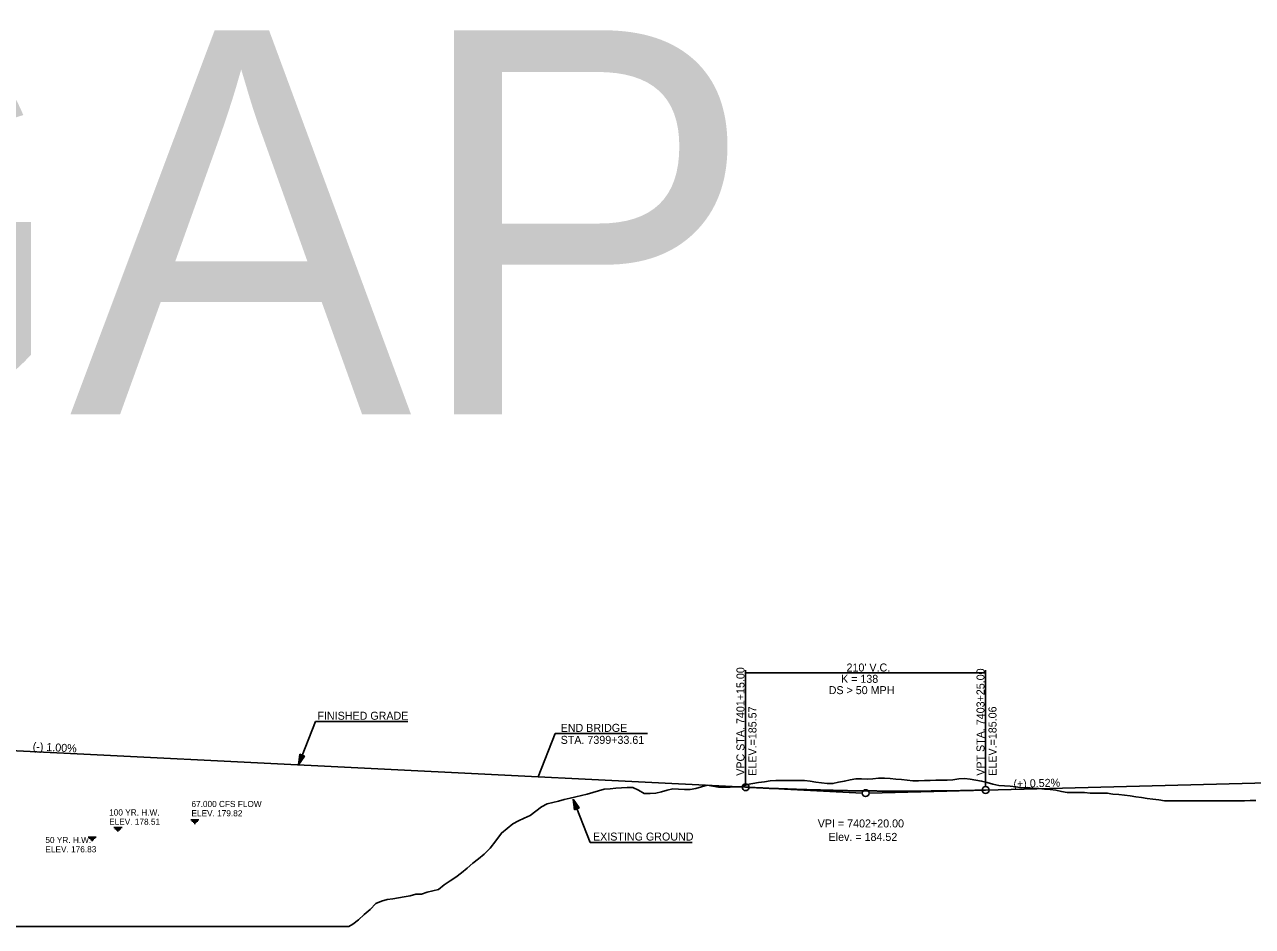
# Model space of a CAD drawing. Extents: x 69 to 2003113, y 512 to 837401.
# Drawn here: x 1917847 to 1918922, y 833588 to 834377 of the extents above; entities that cross this region are included whole.
import ezdxf

# ---------------------------------------------------------------- set-up
doc = ezdxf.new("R2010")
doc.units = 0
for name, color, linetype in [('BR_BORDER LINES', 7, 'Continuous'), ('BR_CENTER LINE BASELINE', 7, 'Continuous'), ('BR_CONCRETE', 7, 'Continuous'), ('BR_GRID DOTS', 7, 'Continuous'), ('BR_GRID LINES', 7, 'Continuous'), ('BR_TEXT', 7, 'Continuous'), ('RD_PD_ALT1_TrvlWay', 7, 'Continuous'), ('RD_SHT_IplotShp', 7, 'Continuous')]:
    doc.layers.add(name, color=color, linetype=linetype)

msp = doc.modelspace()

# ---------------------------------------------------------------- linework, layer by layer
at = {"layer": 'BR_CENTER LINE BASELINE'}
for p, q in [((1918512.2, 833708.3), (1918580.1, 833704.9)), ((1918654.1, 833706.6), (1918586.1, 833704.8))]:
    msp.add_line(p, q, dxfattribs=at)
msp.add_circle((1918583.1, 833704.8), 3, dxfattribs=at)
at = {"layer": 'BR_GRID DOTS'}
for p, q in [((1918478.1, 833812.5), (1918478.1, 833713)), ((1918478.1, 833810), (1918688.1, 833810)), ((1918688.1, 833812.5), (1918688.1, 833710.5))]:
    msp.add_line(p, q, dxfattribs=at)
for centre in [(1918478.1, 833710), (1918688.1, 833707.5)]:
    msp.add_circle(centre, 3, dxfattribs=at)
at = {"layer": 'BR_GRID LINES'}
for p, q in [((1917803.1, 833743.8), (1918478.1, 833710)), ((1918688.1, 833707.5), (1918992.4, 833715.3))]:
    msp.add_line(p, q, dxfattribs=at)
msp.add_spline([(1918478.1, 833710), (1918482.3, 833709.8), (1918486.5, 833709.6), (1918490.7, 833709.4), (1918494.9, 833709.2), (1918499.1, 833709), (1918503.3, 833708.9), (1918507.5, 833708.7), (1918511.7, 833708.5), (1918515.9, 833708.4), (1918520.1, 833708.2), (1918524.3, 833708.1), (1918528.5, 833708), (1918532.7, 833707.8), (1918536.9, 833707.7), (1918541.1, 833707.6), (1918545.3, 833707.5), (1918549.5, 833707.4), (1918553.7, 833707.3), (1918557.9, 833707.2), (1918562.1, 833707.1), (1918566.3, 833707), (1918570.5, 833706.9), (1918574.7, 833706.9), (1918578.9, 833706.8), (1918583.1, 833706.8), (1918587.3, 833706.7), (1918591.5, 833706.7), (1918595.7, 833706.6), (1918599.9, 833706.6), (1918604.1, 833706.6), (1918608.3, 833706.6), (1918612.5, 833706.6), (1918616.7, 833706.6), (1918620.9, 833706.6), (1918625.1, 833706.6), (1918629.3, 833706.6), (1918633.5, 833706.6), (1918637.7, 833706.6), (1918641.9, 833706.7), (1918646.1, 833706.7), (1918650.3, 833706.8), (1918654.5, 833706.8), (1918658.7, 833706.9), (1918662.9, 833706.9), (1918667.1, 833707), (1918671.3, 833707.1), (1918675.5, 833707.2), (1918679.7, 833707.3), (1918683.9, 833707.4), (1918688.1, 833707.5)], degree=3, dxfattribs=at)
at = {"layer": 'BR_TEXT'}
for points in [[(1918194.5, 833616.5), (1918199.5, 833618.1), (1918204.5, 833619.3), (1918209.5, 833620.4), (1918214.5, 833624.7), (1918219.5, 833628), (1918224.5, 833631.3), (1918229.5, 833635.2), (1918234.5, 833639.3), (1918239.5, 833643.4), (1918244.5, 833647.4), (1918249.5, 833651.5), (1918254.5, 833656.7), (1918259.5, 833663.2), (1918264.5, 833669.8), (1918269.5, 833673.9), (1918274.5, 833677.9), (1918279.5, 833680.5), (1918284.5, 833683), (1918289.5, 833685.1), (1918294.5, 833688.9), (1918299.5, 833692.8), (1918304.5, 833695.5), (1918309.5, 833696.7), (1918314.5, 833697.8), (1918319.5, 833699.1), (1918324.5, 833700.3), (1918329.5, 833701.5), (1918334.5, 833702.6), (1918339.5, 833703.9), (1918344.5, 833705.3), (1918349.5, 833706.8), (1918354.5, 833708.2), (1918359.5, 833708.6), (1918364.5, 833709.1), (1918369.5, 833709.5), (1918374.5, 833709.6), (1918379.5, 833709.7), (1918384.5, 833707.4), (1918389.5, 833704.4), (1918394.5, 833704.4), (1918399.5, 833704.8), (1918404.5, 833706), (1918409.5, 833707.3), (1918414.5, 833708.5), (1918419.5, 833708.4), (1918424.5, 833708.1), (1918429.5, 833707.9), (1918434.5, 833708.9), (1918439.5, 833710.4), (1918444.5, 833711.8), (1918449.5, 833711), (1918454.5, 833709.9), (1918459.5, 833710), (1918464.5, 833710.1), (1918469.5, 833710.2), (1918474.5, 833710.3), (1918479.5, 833712.3), (1918484.5, 833713.2), (1918489.5, 833714), (1918494.5, 833714.8), (1918499.5, 833715.6), (1918504.5, 833715.9), (1918509.5, 833715.9), (1918514.5, 833715.9), (1918519.5, 833715.9), (1918524.5, 833715.8), (1918529.5, 833715.8), (1918534.5, 833715.2), (1918539.5, 833714.5), (1918544.5, 833713.8), (1918549.5, 833713.1), (1918554.5, 833713.2), (1918559.5, 833714.3), (1918564.5, 833715.4), (1918569.5, 833716.4), (1918574.5, 833717.3), (1918579.5, 833717.2), (1918584.5, 833717.1), (1918589.5, 833717.3), (1918594.5, 833717.8), (1918599.5, 833718), (1918604.5, 833717.5), (1918609.5, 833717), (1918614.5, 833716.6), (1918619.5, 833716.1), (1918624.5, 833715.5), (1918629.5, 833715.6), (1918634.5, 833715.8), (1918639.5, 833715.9), (1918644.5, 833716), (1918649.5, 833716), (1918654.5, 833716), (1918659.5, 833716.5), (1918664.5, 833717.2), (1918669.5, 833717.5), (1918674.5, 833716.9), (1918679.5, 833716.2), (1918684.5, 833715.4), (1918689.5, 833714), (1918694.5, 833712.6)], [(1918694.5, 833712.6), (1918699.5, 833711.5), (1918704.5, 833711.2), (1918709.5, 833710.9), (1918714.5, 833710.4), (1918719.5, 833709.5), (1918724.5, 833709.6), (1918729.5, 833709.2), (1918734.5, 833708.8), (1918739.5, 833708.4), (1918744.5, 833707.9), (1918749.5, 833707.3), (1918754.5, 833706.3), (1918759.5, 833705.5), (1918764.5, 833705.4), (1918769.5, 833705.4), (1918774.5, 833705.3), (1918779.5, 833704.8), (1918784.5, 833704.9), (1918789.5, 833704.9), (1918794.5, 833704.9), (1918799.5, 833704), (1918804.5, 833703.6), (1918809.5, 833703), (1918814.5, 833702.3), (1918819.5, 833701.6), (1918824.5, 833700.9), (1918829.5, 833700.1), (1918834.5, 833699.5), (1918839.5, 833698.8), (1918844.5, 833698.2), (1918849.5, 833698.2), (1918854.5, 833698.1), (1918859.5, 833698.1), (1918864.5, 833698), (1918869.5, 833698), (1918874.5, 833698.1), (1918879.5, 833698), (1918884.5, 833698), (1918889.5, 833698), (1918894.5, 833698), (1918899.5, 833698.1), (1918904.5, 833698.1), (1918909.5, 833698.1), (1918914.5, 833698.1), (1918919.5, 833698.3), (1918924.5, 833698.4)], [(1917791.3, 833588.2), (1918130.9, 833588.2), (1918134.5, 833590.1), (1918139.5, 833594.1), (1918144.5, 833598.5), (1918149.5, 833602.9), (1918154.5, 833608.2), (1918159.5, 833610.4), (1918164.5, 833611.6), (1918169.5, 833612.4), (1918174.5, 833613.3), (1918179.5, 833614.1), (1918184.5, 833614.9), (1918189.5, 833616.4), (1918194.5, 833616.5)]]:
    msp.add_lwpolyline(points, dxfattribs=at)
at = {"layer": 'RD_PD_ALT1_TrvlWay'}
for p, q in [((1918086.9, 833729.6), (1918101.8, 833767.6)), ((1918101.8, 833767.6), (1918182.6, 833767.6)), ((1918296.7, 833719.1), (1918311.6, 833757)), ((1918311.6, 833757), (1918392.4, 833757)), ((1918086.9, 833729.6), (1918088.1, 833738.8)), ((1918090.2, 833738), (1918086.9, 833729.6)), ((1918086.9, 833729.6), (1918092.3, 833737.2)), ((1918088.1, 833738.8), (1918092.3, 833737.2)), ((1918327.2, 833699.5), (1918342.1, 833661.6)), ((1918330.5, 833691.2), (1918327.2, 833699.5)), ((1918327.2, 833699.5), (1918332.6, 833692)), ((1918327.2, 833699.5), (1918328.4, 833690.3)), ((1918328.4, 833690.3), (1918332.6, 833692)), ((1917992.7, 833681.3), (1917999.8, 833681.3)), ((1917993.7, 833680.3), (1917998.8, 833680.3)), ((1917994.7, 833679.3), (1917997.8, 833679.3)), ((1917925.4, 833674.7), (1917932.6, 833674.7)), ((1917926.4, 833673.7), (1917931.6, 833673.7)), ((1917927.4, 833672.7), (1917930.6, 833672.7)), ((1917928.4, 833671.7), (1917929.6, 833671.7)), ((1917995.7, 833678.3), (1917996.8, 833678.3)), ((1917902.9, 833666.3), (1917910, 833666.3)), ((1917903.9, 833665.3), (1917909, 833665.3)), ((1917904.9, 833664.3), (1917908, 833664.3)), ((1917905.9, 833663.3), (1917907, 833663.3)), ((1918342.1, 833661.6), (1918431.3, 833661.6))]:
    msp.add_line(p, q, dxfattribs=at)
for points in [[(1918090.1, 833737.9), (1918087, 833730.1), (1918090, 833738), (1918087.1, 833730.5), (1918089.9, 833738), (1918087.1, 833730.8), (1918089.8, 833738), (1918087.1, 833731.1), (1918089.8, 833738), (1918087.2, 833731.6), (1918089.6, 833738.1), (1918087.3, 833732.1), (1918089.5, 833738.1), (1918087.4, 833732.5), (1918089.4, 833738.2), (1918087.4, 833733), (1918089.3, 833738.2), (1918087.5, 833733.4), (1918089.3, 833738.3), (1918087.5, 833733.7), (1918089.1, 833738.3), (1918087.6, 833734.2), (1918089, 833738.3), (1918087.7, 833734.8), (1918088.9, 833738.4), (1918087.7, 833735.2), (1918088.8, 833738.4), (1918087.8, 833735.9), (1918088.7, 833738.4), (1918087.9, 833736.4), (1918088.6, 833738.5), (1918087.9, 833736.8), (1918088.5, 833738.5), (1918088, 833737.2), (1918088.4, 833738.6), (1918088, 833737.7), (1918088.3, 833738.6), (1918088.1, 833738.2), (1918088.2, 833738.6)], [(1918087.2, 833730.1), (1918090.2, 833737.9), (1918087.3, 833730.4), (1918090.3, 833737.8), (1918087.5, 833730.6), (1918090.4, 833737.8), (1918087.7, 833730.8), (1918090.4, 833737.8), (1918087.9, 833731.1), (1918090.5, 833737.8), (1918088, 833731.3), (1918090.6, 833737.7), (1918088.2, 833731.6), (1918090.7, 833737.7), (1918088.5, 833732), (1918090.8, 833737.6), (1918088.7, 833732.3), (1918090.9, 833737.7), (1918088.9, 833732.7), (1918091, 833737.6), (1918089.2, 833733), (1918091.1, 833737.6), (1918089.4, 833733.3), (1918091.1, 833737.5), (1918089.7, 833733.8), (1918091.2, 833737.5), (1918090, 833734), (1918091.3, 833737.5), (1918090.3, 833734.4), (1918091.4, 833737.4), (1918090.5, 833734.8), (1918091.5, 833737.4), (1918090.7, 833735.1), (1918091.6, 833737.3), (1918091, 833735.4), (1918091.6, 833737.3), (1918091.2, 833735.9), (1918091.8, 833737.3), (1918091.4, 833736.2), (1918091.9, 833737.2), (1918091.6, 833736.3), (1918092, 833737.1), (1918092.1, 833737.1), (1918092, 833737.1)], [(1918330.4, 833691.2), (1918327.3, 833699), (1918330.3, 833691.2), (1918327.4, 833698.6), (1918330.2, 833691.2), (1918327.4, 833698.4), (1918330.1, 833691.1), (1918327.4, 833698), (1918330, 833691.1), (1918327.5, 833697.5), (1918329.9, 833691), (1918327.6, 833697), (1918329.8, 833691), (1918327.6, 833696.6), (1918329.7, 833691), (1918327.7, 833696.2), (1918329.6, 833691), (1918327.8, 833695.8), (1918329.6, 833690.9), (1918327.8, 833695.4), (1918329.4, 833690.9), (1918327.8, 833694.9), (1918329.3, 833690.8), (1918328, 833694.3), (1918329.2, 833690.7), (1918328, 833693.9), (1918329.1, 833690.7), (1918328.1, 833693.3), (1918329, 833690.7), (1918328.2, 833692.8), (1918328.9, 833690.6), (1918328.2, 833692.3), (1918328.8, 833690.6), (1918328.2, 833691.9), (1918328.7, 833690.5), (1918328.3, 833691.4), (1918328.6, 833690.5), (1918328.4, 833690.9), (1918328.5, 833690.5)], [(1918327.4, 833699), (1918330.5, 833691.3), (1918327.6, 833698.7), (1918330.6, 833691.3), (1918327.8, 833698.5), (1918330.7, 833691.3), (1918327.9, 833698.3), (1918330.7, 833691.4), (1918328.1, 833698), (1918330.8, 833691.4), (1918328.3, 833697.8), (1918330.9, 833691.4), (1918328.5, 833697.5), (1918331, 833691.4), (1918328.8, 833697.1), (1918331.1, 833691.5), (1918329, 833696.8), (1918331.2, 833691.5), (1918329.2, 833696.5), (1918331.3, 833691.5), (1918329.5, 833696.2), (1918331.4, 833691.6), (1918329.7, 833695.8), (1918331.4, 833691.6), (1918330, 833695.4), (1918331.5, 833691.6), (1918330.2, 833695.1), (1918331.6, 833691.6), (1918330.5, 833694.7), (1918331.7, 833691.7), (1918330.8, 833694.3), (1918331.8, 833691.8), (1918331, 833694), (1918331.8, 833691.9), (1918331.3, 833693.7), (1918331.9, 833691.9), (1918331.5, 833693.2), (1918332.1, 833691.9), (1918331.7, 833693), (1918332.2, 833691.9), (1918331.9, 833692.8), (1918332.3, 833692.1), (1918332.4, 833692), (1918332.3, 833692)]]:
    msp.add_lwpolyline(points, dxfattribs=at)

# ---------------------------------------------------------------- texts
at = {"layer": 'BR_BORDER LINES'}
msp.add_text('NOGAP', height=336, dxfattribs=at).set_placement((1916863.1, 834036.2))
at = {"layer": 'BR_CENTER LINE BASELINE'}
for s, rotation, p in [('(-) 1.00%', 357.1375, (1917854.3, 833742.3)), ('(+) 0.52%', 1.479, (1918712.5, 833709.5))]:
    msp.add_text(s, height=7, rotation=rotation, dxfattribs=at).set_placement(p)
at = {"layer": 'BR_CONCRETE'}
for s, p in [('VPC STA. 7401+15.00 ', (1918477.1, 833720)), ('VPT STA. 7403+25.00 ', (1918687.1, 833720)), ('ELEV.=185.57', (1918487.6, 833720)), ('ELEV.=185.06', (1918697.6, 833720))]:
    msp.add_text(s, height=7, rotation=90, dxfattribs=at).set_placement(p)
at = {"layer": 'BR_GRID DOTS'}
for s, p in [('K = 138', (1918561.6, 833801.3)), ("210' V.C.", (1918566.4, 833811.2)), ('DS > 50 MPH', (1918550.8, 833791.4))]:
    msp.add_text(s, height=7, dxfattribs=at).set_placement(p)
at = {"layer": 'RD_PD_ALT1_TrvlWay'}
for s, height, p in [('FINISHED GRADE', 7, (1918103.5, 833769)), ('EXISTING GROUND', 7, (1918344.6, 833663.3)), ('50 YR. H.W.', 5.4, (1917865.5, 833661.1)), ('ELEV. 176.83', 5.4, (1917865.5, 833653))]:
    msp.add_text(s, height=height, dxfattribs=at).set_placement(p)
for s, p in [('100 YR. H.W.', (1917921.3, 833685.2)), ('67.000 CFS FLOW', (1917993.3, 833692.6)), ('ELEV. 179.82', (1917993.3, 833684.5)), ('ELEV. 178.51', (1917921.3, 833677.1))]:
    msp.add_text(s, height=5.4, rotation=360, dxfattribs=at).set_placement(p)
at = {"layer": 'RD_SHT_IplotShp'}
for s, p in [('END BRIDGE', (1918316.3, 833758.4)), ('STA. 7399+33.61', (1918316.3, 833747.9)), ('VPI = 7402+20.00', (1918541.2, 833674.8)), ('Elev. = 184.52', (1918550.7, 833663))]:
    msp.add_text(s, height=7, dxfattribs=at).set_placement(p)

doc.saveas('drawing.dxf')
